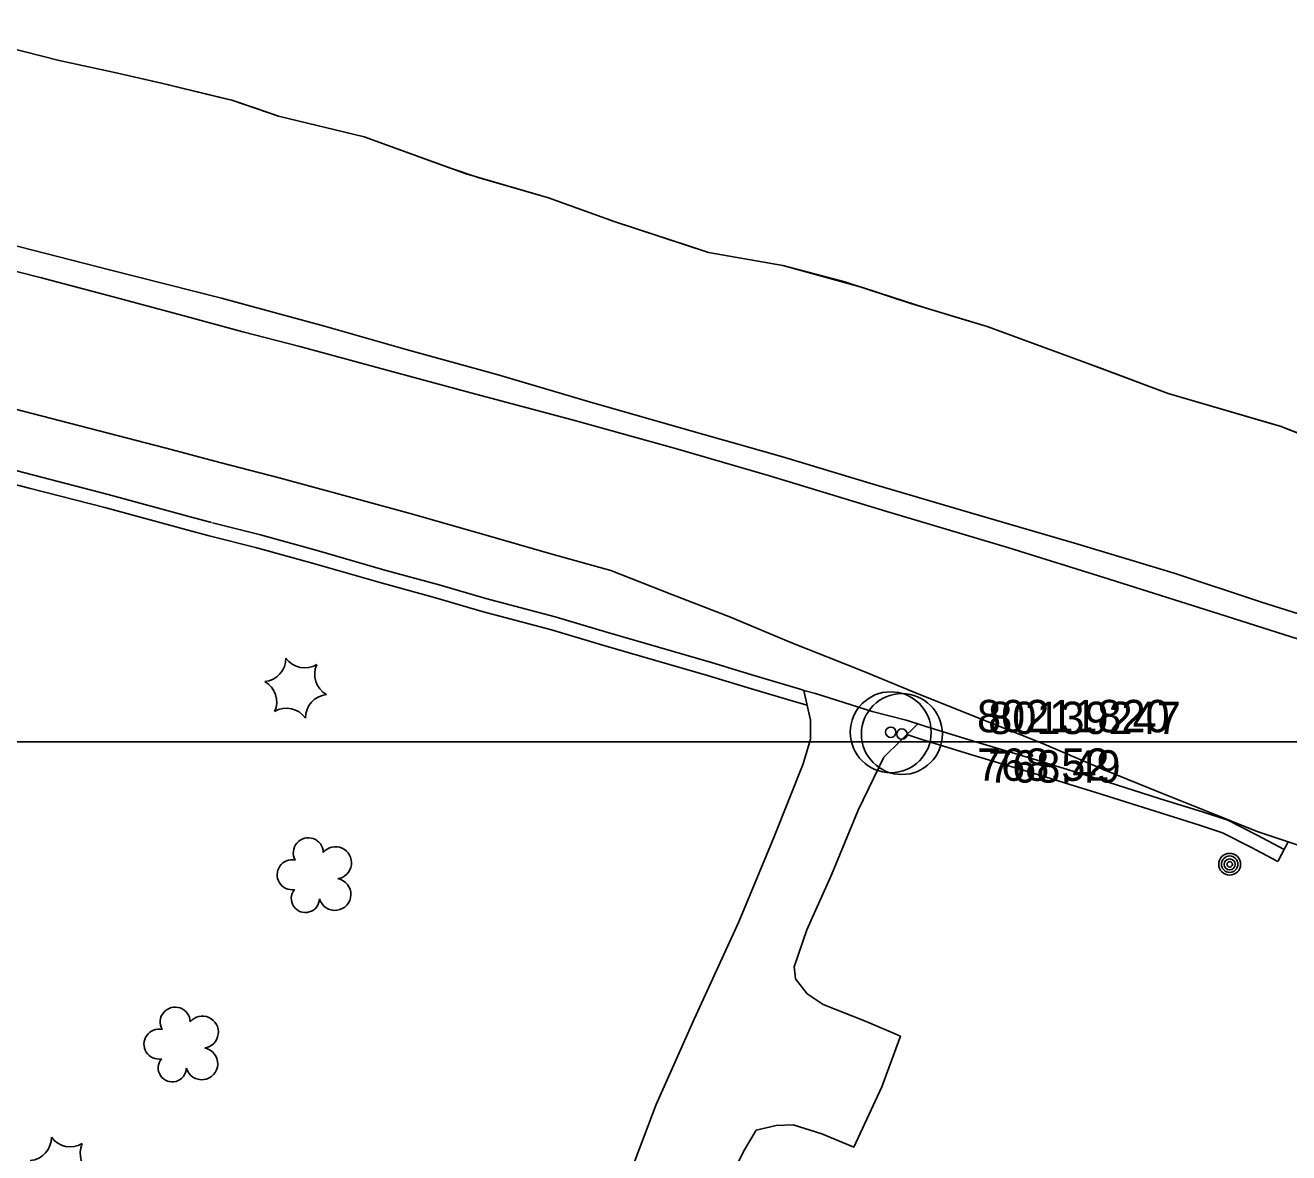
# Model space of a CAD drawing. Extents: x 591954 to 597000, y 198576 to 213500.
# Drawn here: x 595222.2 to 595456.4, y 204423.9 to 204632.8 of the extents above; entities that cross this region are included whole.
import ezdxf

# ---------------------------------------------------------------- set-up
doc = ezdxf.new("R2010")
doc.units = 0
for name, color, linetype in [('Level 10', 7, 'Continuous'), ('Level 11', 7, 'Continuous'), ('Level 14', 7, 'Continuous'), ('Level 17', 7, 'Continuous'), ('Level 18', 7, 'Continuous'), ('Level 19', 7, 'Continuous'), ('Level 6', 7, 'Continuous')]:
    doc.layers.add(name, color=color, linetype=linetype)

msp = doc.modelspace()

# ---------------------------------------------------------------- linework, layer by layer
at = {"layer": 'Level 10'}
for p, q in [((593000, 204500), (595500, 204500)), ((593500, 204500), (595500, 204500)), ((593500, 204500), (595500, 204500)), ((593500, 204500), (595500, 204500)), ((595000, 204500), (597000, 204500)), ((595000, 204500), (597000, 204500)), ((595000, 204500), (596500, 204500)), ((595000, 204500), (597000, 204500))]:
    msp.add_line(p, q, dxfattribs=at)
at = {"layer": 'Level 11'}
for points in [[(595005.86, 204647.05), (595024.86, 204641.67), (595041.9, 204637.49), (595056.66, 204633.54), (595070.43, 204630.34), (595086.32, 204626.2), (595101.34, 204622.24), (595116.19, 204618.3), (595135.83, 204613.2), (595152.76, 204609.04), (595175.42, 204603.27), (595195.76, 204598.05), (595218.8, 204592.36), (595237.83, 204587.45), (595258.62, 204582.22), (595263.39, 204580.93)], [(594920.11, 204626.29), (594929.43, 204625.11), (594944.34, 204622.44), (594960.83, 204619.1), (594979.1, 204615.35), (594995.08, 204612.07), (595011.29, 204608.67), (595032.2, 204604.07), (595047.39, 204600.89), (595068.67, 204596.46), (595088.03, 204592.56), (595107.19, 204588.7), (595124.89, 204585.02), (595141.21, 204581.6), (595158.77, 204577.41), (595175.05, 204573.35), (595193.87, 204568.54), (595209.58, 204564.41), (595228.78, 204559.47), (595248.11, 204554.48), (595258.57, 204551.71)], [(595262.58, 204576), (595251.43, 204579.04), (595237.86, 204582.65), (595224.97, 204586.04), (595210.37, 204589.77)], [(595579.15, 204484.03), (595573.97, 204485.46), (595562.15, 204489.45), (595547.75, 204494.46), (595531.3, 204500.26), (595514.53, 204505.86), (595499.55, 204510.74), (595484.07, 204515.62), (595466.27, 204521.21), (595451.43, 204525.9), (595435.2, 204531.26), (595417.18, 204536.73), (595397.88, 204542.34), (595379.44, 204547.78), (595362.44, 204552.91), (595344.31, 204558.02), (595326.4, 204563.13), (595309.92, 204568.05), (595292.84, 204572.74), (595277.73, 204577.01), (595263.39, 204580.93)], [(595579.15, 204484.03), (595573.97, 204485.46), (595562.15, 204489.45), (595547.75, 204494.46), (595531.3, 204500.26), (595514.53, 204505.86), (595499.55, 204510.74), (595484.07, 204515.62), (595466.27, 204521.21), (595451.43, 204525.9), (595435.2, 204531.26), (595417.18, 204536.73), (595397.88, 204542.34), (595379.44, 204547.78), (595362.44, 204552.91), (595344.31, 204558.02), (595326.4, 204563.13), (595309.92, 204568.05), (595292.84, 204572.74), (595277.73, 204577.01), (595263.39, 204580.93)], [(595579.15, 204484.03), (595573.97, 204485.46), (595562.15, 204489.45), (595547.75, 204494.46), (595531.3, 204500.26), (595514.53, 204505.86), (595499.55, 204510.74), (595484.07, 204515.62), (595466.27, 204521.21), (595451.43, 204525.9), (595435.2, 204531.26), (595417.18, 204536.73), (595397.88, 204542.34), (595379.44, 204547.78), (595362.44, 204552.91), (595344.31, 204558.02), (595326.4, 204563.13), (595309.92, 204568.05), (595292.84, 204572.74), (595277.73, 204577.01), (595263.39, 204580.93)], [(595262.58, 204576), (595273.15, 204573.3), (595288.17, 204569.2), (595304.84, 204564.67), (595323.84, 204559.59), (595342.79, 204554.35), (595360.18, 204549.32), (595381.95, 204542.7), (595404.55, 204535.94), (595423.17, 204530.14), (595443.51, 204523.73), (595463.69, 204517.3), (595483.99, 204510.74), (595501.93, 204504.83), (595519.75, 204498.95), (595539.44, 204492.24), (595552.5, 204487.77), (595568.7, 204485.23), (595582.16, 204483.69), (595597.53, 204480.96), (595608.51, 204479.26), (595616.06, 204478.17)], [(595262.58, 204576), (595273.15, 204573.3), (595288.17, 204569.2), (595304.84, 204564.67), (595323.84, 204559.59), (595342.79, 204554.35), (595360.18, 204549.32), (595381.95, 204542.7), (595404.55, 204535.94), (595423.17, 204530.14), (595443.51, 204523.73), (595463.69, 204517.3), (595483.99, 204510.74), (595501.93, 204504.83), (595519.75, 204498.95), (595539.44, 204492.24), (595552.5, 204487.77), (595568.7, 204485.23), (595582.16, 204483.69), (595597.53, 204480.96), (595608.51, 204479.26), (595616.06, 204478.17)], [(595262.58, 204576), (595273.15, 204573.3), (595288.17, 204569.2), (595304.84, 204564.67), (595323.84, 204559.59), (595342.79, 204554.35), (595360.18, 204549.32), (595381.95, 204542.7), (595404.55, 204535.94), (595423.17, 204530.14), (595443.51, 204523.73), (595463.69, 204517.3), (595483.99, 204510.74), (595501.93, 204504.83), (595519.75, 204498.95), (595539.44, 204492.24), (595552.5, 204487.77), (595568.7, 204485.23), (595582.16, 204483.69), (595597.53, 204480.96), (595608.51, 204479.26), (595616.06, 204478.17)], [(595163.1, 204564.93), (595177.83, 204561.34), (595192.63, 204557.54), (595207.41, 204553.66), (595223.56, 204549.46), (595237.63, 204545.85), (595252.82, 204541.69), (595256.74, 204540.65)], [(595162.51, 204562.51), (595177.22, 204558.91), (595192, 204555.12), (595206.78, 204551.24), (595222.93, 204547.04), (595236.99, 204543.43), (595252.17, 204539.28), (595256.33, 204538.18)], [(595258.57, 204551.71), (595269.27, 204548.95), (595280.65, 204545.83), (595293.57, 204542.3), (595306.8, 204538.55), (595319.69, 204534.86), (595330.77, 204531.78), (595342.11, 204527.3), (595352.98, 204523.09), (595364.16, 204518.44), (595377.53, 204513.12), (595386.82, 204509.28), (595398.68, 204504.54), (595410.67, 204499.74), (595422.23, 204494.82), (595432.77, 204490.57), (595441.41, 204487.07), (595450.6, 204483.4), (595456.36, 204481.49)], [(595258.57, 204551.71), (595269.27, 204548.95), (595280.65, 204545.83), (595293.57, 204542.3), (595306.8, 204538.55), (595319.69, 204534.86), (595330.77, 204531.78), (595342.11, 204527.3), (595352.98, 204523.09), (595364.16, 204518.44), (595377.53, 204513.12), (595386.82, 204509.28), (595398.68, 204504.54), (595410.67, 204499.74), (595422.23, 204494.82), (595432.77, 204490.57), (595441.41, 204487.07), (595450.6, 204483.4), (595456.36, 204481.49)], [(595258.57, 204551.71), (595269.27, 204548.95), (595280.65, 204545.83), (595293.57, 204542.3), (595306.8, 204538.55), (595319.69, 204534.86), (595330.77, 204531.78), (595342.11, 204527.3), (595352.98, 204523.09), (595364.16, 204518.44), (595377.53, 204513.12), (595386.82, 204509.28), (595398.68, 204504.54), (595410.67, 204499.74), (595422.23, 204494.82), (595432.77, 204490.57), (595441.41, 204487.07), (595450.6, 204483.4), (595456.36, 204481.49)], [(595256.94, 204540.6), (595265.81, 204538.38), (595276.33, 204535.45), (595288.91, 204531.85), (595298.93, 204529.08), (595307.63, 204526.58), (595320.47, 204523.17), (595330.21, 204520.25), (595339.59, 204517.57), (595349.43, 204514.68), (595356.95, 204512.43), (595365.89, 204509.74), (595366.58, 204509.55)], [(595256.94, 204540.6), (595265.81, 204538.38), (595276.33, 204535.45), (595288.91, 204531.85), (595298.93, 204529.08), (595307.63, 204526.58), (595320.47, 204523.17), (595330.21, 204520.25), (595339.59, 204517.57), (595349.43, 204514.68), (595356.95, 204512.43), (595365.89, 204509.74), (595366.58, 204509.55)], [(595256.94, 204540.6), (595265.81, 204538.38), (595276.33, 204535.45), (595288.91, 204531.85), (595298.93, 204529.08), (595307.63, 204526.58), (595320.47, 204523.17), (595330.21, 204520.25), (595339.59, 204517.57), (595349.43, 204514.68), (595356.95, 204512.43), (595365.89, 204509.74), (595366.58, 204509.55)], [(595256.33, 204538.18), (595265.17, 204535.96), (595275.65, 204533.05), (595288.23, 204529.45), (595298.25, 204526.68), (595306.96, 204524.17), (595319.79, 204520.77), (595329.51, 204517.85), (595338.9, 204515.17), (595348.71, 204512.29), (595356.23, 204510.03), (595365.2, 204507.34), (595367.18, 204506.79)], [(595256.33, 204538.18), (595265.17, 204535.96), (595275.65, 204533.05), (595288.23, 204529.45), (595298.25, 204526.68), (595306.96, 204524.17), (595319.79, 204520.77), (595329.51, 204517.85), (595338.9, 204515.17), (595348.71, 204512.29), (595356.23, 204510.03), (595365.2, 204507.34), (595367.18, 204506.79)], [(595256.33, 204538.18), (595265.17, 204535.96), (595275.65, 204533.05), (595288.23, 204529.45), (595298.25, 204526.68), (595306.96, 204524.17), (595319.79, 204520.77), (595329.51, 204517.85), (595338.9, 204515.17), (595348.71, 204512.29), (595356.23, 204510.03), (595365.2, 204507.34), (595367.18, 204506.79)], [(595366.58, 204509.55), (595368.72, 204508.96)], [(595366.58, 204509.55), (595368.72, 204508.96)], [(595366.58, 204509.55), (595368.72, 204508.96)], [(595368.72, 204508.96), (595379.25, 204505.6), (595385.52, 204504)], [(595368.72, 204508.96), (595379.25, 204505.6), (595385.52, 204504)], [(595368.72, 204508.96), (595379.25, 204505.6), (595385.52, 204504)], [(595385.52, 204504), (595387.71, 204503.32)], [(595385.52, 204504), (595387.71, 204503.32)], [(595385.52, 204504), (595387.71, 204503.32)], [(595385.67, 204501.34), (595388.27, 204500.53), (595397.3, 204497.72), (595409.07, 204494.19), (595420.7, 204490.63), (595431.68, 204487.13), (595439.88, 204484.59), (595444.2, 204483.15), (595449.45, 204480.49), (595454.45, 204477.85)], [(595385.67, 204501.34), (595388.27, 204500.53), (595397.3, 204497.72), (595409.07, 204494.19), (595420.7, 204490.63), (595431.68, 204487.13), (595439.88, 204484.59), (595444.2, 204483.15), (595449.45, 204480.49), (595454.45, 204477.85)], [(595385.67, 204501.34), (595388.27, 204500.53), (595397.3, 204497.72), (595409.07, 204494.19), (595420.7, 204490.63), (595431.68, 204487.13), (595439.88, 204484.59), (595444.2, 204483.15), (595449.45, 204480.49), (595454.45, 204477.85)], [(595387.71, 204503.32), (595389.01, 204502.92), (595398.03, 204500.11), (595409.8, 204496.58), (595421.45, 204493.02), (595432.43, 204489.51), (595440.64, 204486.97), (595445.17, 204485.47), (595450.6, 204482.71), (595455.61, 204480.07)], [(595387.71, 204503.32), (595389.01, 204502.92), (595398.03, 204500.11), (595409.8, 204496.58), (595421.45, 204493.02), (595432.43, 204489.51), (595440.64, 204486.97), (595445.17, 204485.47), (595450.6, 204482.71), (595455.61, 204480.07)], [(595387.71, 204503.32), (595389.01, 204502.92), (595398.03, 204500.11), (595409.8, 204496.58), (595421.45, 204493.02), (595432.43, 204489.51), (595440.64, 204486.97), (595445.17, 204485.47), (595450.6, 204482.71), (595455.61, 204480.07)], [(595456.36, 204481.49), (595454.49, 204477.94), (595454.45, 204477.85)], [(595456.36, 204481.49), (595454.49, 204477.94), (595454.45, 204477.85)], [(595456.36, 204481.49), (595454.49, 204477.94), (595454.45, 204477.85)], [(595456.36, 204481.49), (595461.22, 204479.88), (595472.9, 204476.55), (595483.79, 204473.21), (595495.93, 204469.43), (595508.49, 204465.7), (595522.23, 204461.48), (595536.36, 204456.81), (595548, 204452.97), (595561.19, 204448.29), (595573.06, 204443.99), (595586.1, 204439.27), (595599.65, 204434.39), (595612.15, 204429.84), (595625.92, 204424.92)], [(595456.36, 204481.49), (595461.22, 204479.88), (595472.9, 204476.55), (595483.79, 204473.21), (595495.93, 204469.43), (595508.49, 204465.7), (595522.23, 204461.48), (595536.36, 204456.81), (595548, 204452.97), (595561.19, 204448.29), (595573.06, 204443.99), (595586.1, 204439.27), (595599.65, 204434.39), (595612.15, 204429.84), (595625.92, 204424.92)], [(595456.36, 204481.49), (595461.22, 204479.88), (595472.9, 204476.55), (595483.79, 204473.21), (595495.93, 204469.43), (595508.49, 204465.7), (595522.23, 204461.48), (595536.36, 204456.81), (595548, 204452.97), (595561.19, 204448.29), (595573.06, 204443.99), (595586.1, 204439.27), (595599.65, 204434.39), (595612.15, 204429.84), (595625.92, 204424.92)]]:
    msp.add_lwpolyline(points, dxfattribs=at)
at = {"layer": 'Level 14'}
for centre, radius in [((595445.5, 204477.32), 2.02), ((595445.5, 204477.33), 1.52), ((595445.5, 204477.29), 1.01), ((595445.51, 204477.3), 0.502)]:
    msp.add_circle(centre, radius, dxfattribs=at)
at = {"layer": 'Level 17'}
for points in [[(595366.58, 204509.55), (595367.78, 204504), (595367.77, 204500.52), (595366.45, 204495.91), (595360.99, 204482.26), (595354.48, 204466.68), (595346.22, 204448.6), (595339.21, 204432.79), (595335.44, 204422.88), (595334.02, 204419.01)], [(595366.58, 204509.55), (595367.78, 204504), (595367.77, 204500.52), (595366.45, 204495.91), (595360.99, 204482.26), (595354.48, 204466.68), (595346.22, 204448.6), (595339.21, 204432.79), (595335.44, 204422.88), (595334.02, 204419.01)], [(595366.58, 204509.55), (595367.78, 204504), (595367.77, 204500.52), (595366.45, 204495.91), (595360.99, 204482.26), (595354.48, 204466.68), (595346.22, 204448.6), (595339.21, 204432.79), (595335.44, 204422.88), (595334.02, 204419.01)], [(595387.71, 204503.32), (595381.37, 204497.15), (595376.61, 204487.34), (595371.7, 204475.33), (595367.12, 204465.16), (595364.74, 204458.34), (595365.02, 204456.07), (595367.18, 204453.33), (595370.14, 204451.3), (595378.13, 204448.15), (595384.48, 204445.43), (595381.01, 204436.09), (595375.81, 204424.86), (595369.89, 204427.37), (595364.58, 204429.02), (595361.44, 204428.92), (595357.73, 204428.07), (595355.35, 204424.1), (595349.33, 204411.57), (595349.2, 204411.31)], [(595387.71, 204503.32), (595381.37, 204497.15), (595376.61, 204487.34), (595371.7, 204475.33), (595367.12, 204465.16), (595364.74, 204458.34), (595365.02, 204456.07), (595367.18, 204453.33), (595370.14, 204451.3), (595378.13, 204448.15), (595384.48, 204445.43), (595381.01, 204436.09), (595375.81, 204424.86), (595369.89, 204427.37), (595364.58, 204429.02), (595361.44, 204428.92), (595357.73, 204428.07), (595355.35, 204424.1), (595349.33, 204411.57), (595349.2, 204411.31)], [(595387.71, 204503.32), (595381.37, 204497.15), (595376.61, 204487.34), (595371.7, 204475.33), (595367.12, 204465.16), (595364.74, 204458.34), (595365.02, 204456.07), (595367.18, 204453.33), (595370.14, 204451.3), (595378.13, 204448.15), (595384.48, 204445.43), (595381.01, 204436.09), (595375.81, 204424.86), (595369.89, 204427.37), (595364.58, 204429.02), (595361.44, 204428.92), (595357.73, 204428.07), (595355.35, 204424.1), (595349.33, 204411.57), (595349.2, 204411.31)]]:
    msp.add_lwpolyline(points, dxfattribs=at)
at = {"layer": 'Level 18'}
for centre, radius, start, end in [((595266.24, 204515.47), 4.3, 275.2113, 0.9762), ((595266.24, 204515.47), 4.3, 275.2113, 0.9762), ((595266.24, 204515.47), 4.3, 275.2113, 0.9762), ((595274.06, 204518.02), 4.3, 215.2113, 300.9762), ((595274.06, 204518.02), 4.3, 215.2113, 300.9762), ((595274.06, 204518.02), 4.3, 215.2113, 300.9762), ((595280.18, 204512.53), 4.3, 155.2113, 240.9762), ((595280.18, 204512.53), 4.3, 155.2113, 240.9762), ((595280.18, 204512.53), 4.3, 155.2113, 240.9762), ((595264.55, 204507.42), 4.3, 335.2113, 60.9762), ((595264.55, 204507.42), 4.3, 335.2113, 60.9762), ((595264.55, 204507.42), 4.3, 335.2113, 60.9762), ((595278.48, 204504.48), 4.3, 95.2113, 180.9762), ((595278.48, 204504.48), 4.3, 95.2113, 180.9762), ((595278.48, 204504.48), 4.3, 95.2113, 180.9762), ((595270.67, 204501.93), 4.3, 35.2113, 120.9762), ((595270.67, 204501.93), 4.3, 35.2113, 120.9762), ((595270.67, 204501.93), 4.3, 35.2113, 120.9762), ((595274.7, 204479.45), 2.78, 1.3946, 209.1675), ((595274.7, 204479.45), 2.78, 1.3946, 209.1675), ((595274.7, 204479.45), 2.78, 1.3946, 209.1675), ((595279.74, 204477.59), 2.97, 278.4237, 139.6575), ((595279.74, 204477.59), 2.97, 278.4237, 139.6575), ((595279.74, 204477.59), 2.97, 278.4237, 139.6575), ((595271.7, 204475.38), 2.78, 78.0716, 279.0826), ((595271.7, 204475.38), 2.78, 78.0716, 279.0826), ((595271.7, 204475.38), 2.78, 78.0716, 279.0826), ((595279.63, 204471.74), 2.97, 196.0745, 79.0477), ((595279.63, 204471.74), 2.97, 196.0745, 79.0477), ((595279.63, 204471.74), 2.97, 196.0745, 79.0477), ((595274.16, 204470.98), 2.61, 140.7797, 358.7123), ((595274.16, 204470.98), 2.61, 140.7797, 358.7123), ((595274.16, 204470.98), 2.61, 140.7797, 358.7123), ((595250.02, 204448.07), 2.78, 1.3946, 209.1675), ((595250.02, 204448.07), 2.78, 1.3946, 209.1675), ((595250.02, 204448.07), 2.78, 1.3946, 209.1675), ((595255.06, 204446.21), 2.97, 278.4237, 139.6575), ((595255.06, 204446.21), 2.97, 278.4237, 139.6575), ((595255.06, 204446.21), 2.97, 278.4237, 139.6575), ((595247.02, 204443.99), 2.78, 78.0716, 279.0826), ((595247.02, 204443.99), 2.78, 78.0716, 279.0826), ((595247.02, 204443.99), 2.78, 78.0716, 279.0826), ((595254.95, 204440.35), 2.97, 196.0745, 79.0477), ((595254.95, 204440.35), 2.97, 196.0745, 79.0477), ((595254.95, 204440.35), 2.97, 196.0745, 79.0477), ((595249.48, 204439.59), 2.61, 140.7797, 358.7123), ((595249.48, 204439.59), 2.61, 140.7797, 358.7123), ((595249.48, 204439.59), 2.61, 140.7797, 358.7123), ((595222.78, 204426.7), 4.3, 275.2113, 0.9762), ((595230.59, 204429.25), 4.3, 215.2113, 300.9762), ((595236.71, 204423.76), 4.3, 155.2113, 240.9762)]:
    msp.add_arc(centre, radius, start, end, dxfattribs=at)
at = {"layer": 'Level 19'}
for p, q in [((595253.57, 204620.6), (595247.75, 204622.02)), ((595259.4, 204619.17), (595253.57, 204620.6)), ((595269.18, 204615.98), (595265.11, 204617.35)), ((595306.4, 204604.54), (595300.71, 204606.44)), ((595312.16, 204602.86), (595306.4, 204604.54)), ((595317.92, 204601.18), (595312.16, 204602.86)), ((595383.12, 204582.33), (595377.42, 204584.21)), ((595388.84, 204580.52), (595383.12, 204582.33)), ((595394.58, 204578.77), (595388.84, 204580.52))]:
    msp.add_line(p, q, dxfattribs=at)
for points in [[(595247.75, 204622.02), (595238.5, 204624.09), (595228.53, 204626.26), (595218.59, 204628.8), (595215.63, 204629.58)], [(595218.59, 204628.8), (595228.53, 204626.26), (595238.5, 204624.09), (595247.51, 204622.08), (595260.51, 204618.9), (595269.18, 204615.98)], [(595265.11, 204617.35), (595260.51, 204618.9), (595259.4, 204619.17)], [(595269.18, 204615.98), (595285.05, 204612.15), (595303.99, 204605.25), (595319.22, 204600.8), (595331.39, 204596.42), (595348.91, 204590.69), (595362.65, 204588.29), (595374.15, 204585.28), (595386.38, 204581.26), (595400.57, 204576.95), (595418.72, 204570.3), (595434.1, 204564.57), (595454.86, 204558.49), (595471.11, 204552.25), (595487.5, 204546.79), (595502.06, 204542.53), (595516.79, 204537.94), (595530.25, 204533.98), (595547.33, 204527.04), (595562.44, 204521.01), (595580.88, 204514.24), (595595.6, 204509.72), (595609.04, 204504.22), (595621.06, 204501.46)], [(595269.18, 204615.98), (595285.05, 204612.15), (595303.99, 204605.25), (595319.22, 204600.8), (595331.39, 204596.42), (595348.91, 204590.69), (595362.65, 204588.29), (595374.15, 204585.28), (595386.38, 204581.26), (595400.57, 204576.95), (595418.72, 204570.3), (595434.1, 204564.57), (595454.86, 204558.49), (595471.11, 204552.25), (595487.5, 204546.79), (595502.06, 204542.53), (595516.79, 204537.94), (595530.25, 204533.98), (595547.33, 204527.04), (595562.44, 204521.01), (595580.88, 204514.24), (595595.6, 204509.72), (595609.04, 204504.22), (595621.06, 204501.46)], [(595269.18, 204615.98), (595285.05, 204612.15), (595303.99, 204605.25), (595319.22, 204600.8), (595331.39, 204596.42), (595348.91, 204590.69), (595362.65, 204588.29), (595374.15, 204585.28), (595386.38, 204581.26), (595400.57, 204576.95), (595418.72, 204570.3), (595434.1, 204564.57), (595454.86, 204558.49), (595471.11, 204552.25), (595487.5, 204546.79), (595502.06, 204542.53), (595516.79, 204537.94), (595530.25, 204533.98), (595547.33, 204527.04), (595562.44, 204521.01), (595580.88, 204514.24), (595595.6, 204509.72), (595609.04, 204504.22), (595621.06, 204501.46)], [(595300.71, 204606.44), (595285.05, 204612.15), (595269.18, 204615.98)], [(595345.37, 204591.85), (595331.39, 204596.42), (595319.22, 204600.8), (595317.92, 204601.18)], [(595377.42, 204584.21), (595362.65, 204588.29), (595348.91, 204590.69), (595345.37, 204591.85)], [(595421.92, 204569.11), (595418.72, 204570.3), (595400.57, 204576.95), (595394.58, 204578.77)], [(595453.29, 204558.95), (595434.1, 204564.57), (595421.92, 204569.11)], [(595458.93, 204556.92), (595454.86, 204558.49), (595453.29, 204558.95)]]:
    msp.add_lwpolyline(points, dxfattribs=at)
at = {"layer": 'Level 6'}
for centre, radius in [((595382.67, 204501.78), 7.5), ((595382.67, 204501.78), 7.5), ((595382.67, 204501.78), 7.5), ((595382.67, 204501.78), 7.5), ((595382.67, 204501.78), 7.5), ((595382.67, 204501.78), 7.5), ((595382.67, 204501.78), 7.5), ((595384.74, 204501.45), 7.5), ((595384.74, 204501.45), 7.5), ((595384.74, 204501.45), 7.5), ((595384.74, 204501.45), 7.5), ((595384.74, 204501.45), 7.5), ((595384.74, 204501.45), 7.5), ((595384.74, 204501.45), 7.5), ((595382.67, 204501.78), 0.96), ((595382.67, 204501.78), 0.96), ((595382.67, 204501.78), 0.96), ((595382.67, 204501.78), 0.96), ((595382.67, 204501.78), 0.96), ((595382.67, 204501.78), 0.96), ((595382.67, 204501.78), 0.96), ((595384.74, 204501.45), 0.96), ((595384.74, 204501.45), 0.96), ((595384.74, 204501.45), 0.96), ((595384.74, 204501.45), 0.96), ((595384.74, 204501.45), 0.96), ((595384.74, 204501.45), 0.96), ((595384.74, 204501.45), 0.96)]:
    msp.add_circle(centre, radius, dxfattribs=at)

# ---------------------------------------------------------------- texts
for s, p in [('80211820', (595398.67, 204501.78)), ('80211820', (595398.67, 204501.78)), ('80211820', (595398.67, 204501.78)), ('80211820', (595398.67, 204501.78)), ('80211820', (595398.67, 204501.78)), ('80211820', (595398.67, 204501.78)), ('80211820', (595398.67, 204501.78)), ('80139247', (595400.74, 204501.45)), ('80139247', (595400.74, 204501.45)), ('80139247', (595400.74, 204501.45)), ('80139247', (595400.74, 204501.45)), ('80139247', (595400.74, 204501.45)), ('80139247', (595400.74, 204501.45)), ('80139247', (595400.74, 204501.45)), ('768.52', (595398.67, 204492.78)), ('768.52', (595398.67, 204492.78)), ('768.52', (595398.67, 204492.78)), ('768.52', (595398.67, 204492.78)), ('768.52', (595398.67, 204492.78)), ('768.52', (595398.67, 204492.78)), ('768.52', (595398.67, 204492.78)), ('768.49', (595400.74, 204492.45)), ('768.49', (595400.74, 204492.45)), ('768.49', (595400.74, 204492.45)), ('768.49', (595400.74, 204492.45)), ('768.49', (595400.74, 204492.45)), ('768.49', (595400.74, 204492.45)), ('768.49', (595400.74, 204492.45))]:
    msp.add_text(s, height=6, dxfattribs=at).set_placement(p)

doc.saveas('drawing.dxf')
